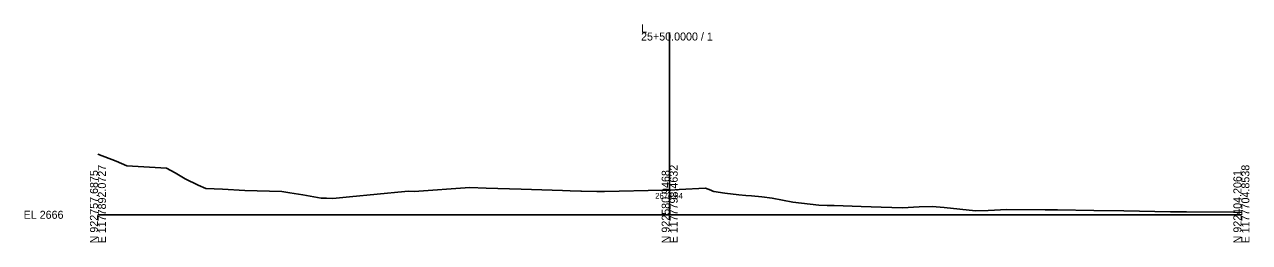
# Model space of a CAD drawing. Extents: x -26 to 1403, y -10 to 9563.
# Drawn here: x 974.3 to 1402.8, y 5490.3 to 5566.5 of the extents above; entities that cross this region are included whole.
import ezdxf

# ---------------------------------------------------------------- set-up
doc = ezdxf.new("R2010")
doc.units = 0
for name, color, linetype in [('Exist Cross Section Cell', 7, 'Continuous'), ('Exist XS Center Line Elevation Label', 7, 'Continuous'), ('Exist XS Ground Line', 7, 'Continuous')]:
    doc.layers.add(name, color=color, linetype=linetype)

msp = doc.modelspace()

# ---------------------------------------------------------------- linework, layer by layer
at = {"layer": 'Exist Cross Section Cell'}
for p, q in [((1200, 5500), (1200, 5563.74)), ((1000, 5500), (1200, 5500)), ((1200, 5500), (1400, 5500))]:
    msp.add_line(p, q, dxfattribs=at)
at = {"layer": 'Exist XS Ground Line'}
for p, q in [((1000, 5521.25), (1006.37, 5518.69)), ((1006.37, 5518.69), (1010.09, 5517.08)), ((1010.09, 5517.08), (1021.98, 5516.42)), ((1021.98, 5516.42), (1023.97, 5516.32)), ((1023.97, 5516.32), (1026.99, 5514.61)), ((1026.99, 5514.61), (1030.47, 5512.6)), ((1030.47, 5512.6), (1035.04, 5510.33)), ((1035.04, 5510.33), (1037.71, 5509.21)), ((1037.71, 5509.21), (1043.54, 5508.94)), ((1043.54, 5508.94), (1051.42, 5508.54)), ((1051.42, 5508.54), (1064.36, 5508.19)), ((1064.36, 5508.19), (1067.11, 5507.71)), ((1067.11, 5507.71), (1071.65, 5506.94)), ((1071.65, 5506.94), (1075.51, 5506.24)), ((1088, 5506.26), (1107.38, 5508.12)), ((1107.38, 5508.12), (1108.68, 5508.3)), ((1108.68, 5508.3), (1110.66, 5508.19)), ((1110.66, 5508.19), (1130.05, 5509.51)), ((1130.05, 5509.51), (1135.76, 5509.35)), ((1135.76, 5509.35), (1148.06, 5508.91)), ((1148.06, 5508.91), (1162.56, 5508.5)), ((1162.56, 5508.5), (1165.22, 5508.4)), ((1165.22, 5508.4), (1168.88, 5508.3)), ((1168.88, 5508.3), (1169.19, 5508.3)), ((1169.19, 5508.3), (1174.53, 5508.15)), ((1174.53, 5508.15), (1174.96, 5508.14)), ((1174.96, 5508.14), (1176.79, 5508.11)), ((1176.79, 5508.11), (1177.26, 5508.1)), ((1177.26, 5508.1), (1197.62, 5508.59)), ((1197.62, 5508.59), (1198.72, 5508.6)), ((1198.72, 5508.6), (1199.33, 5508.62)), ((1199.33, 5508.62), (1200, 5508.64)), ((1200, 5508.64), (1200.4, 5508.65)), ((1200.4, 5508.65), (1203.36, 5508.82)), ((1203.36, 5508.82), (1212.5, 5509.35)), ((1212.5, 5509.35), (1214.42, 5508.55)), ((1214.42, 5508.55), (1215.09, 5508.27)), ((1215.09, 5508.27), (1215.44, 5508.19)), ((1215.44, 5508.19), (1219.25, 5507.5)), ((1219.25, 5507.5), (1224.22, 5506.98)), ((1224.22, 5506.98), (1226.61, 5506.72)), ((1226.61, 5506.72), (1228.57, 5506.58)), ((1075.51, 5506.24), (1078.11, 5505.84)), ((1078.11, 5505.84), (1080.01, 5505.76)), ((1080.01, 5505.76), (1082.18, 5505.69)), ((1082.18, 5505.69), (1088, 5506.26)), ((1228.57, 5506.58), (1232.26, 5506.23)), ((1232.26, 5506.23), (1235.87, 5505.84)), ((1235.87, 5505.84), (1243.09, 5504.39)), ((1243.09, 5504.39), (1252.23, 5503.36)), ((1252.23, 5503.36), (1255.07, 5503.25)), ((1255.07, 5503.25), (1257.56, 5503.22)), ((1257.56, 5503.22), (1266.99, 5502.92)), ((1266.99, 5502.92), (1273.96, 5502.66)), ((1273.96, 5502.66), (1281.47, 5502.45)), ((1281.47, 5502.45), (1287.25, 5502.74)), ((1287.25, 5502.74), (1291.78, 5502.89)), ((1291.78, 5502.89), (1296.04, 5502.52)), ((1296.04, 5502.52), (1306.95, 5501.34)), ((1306.95, 5501.34), (1311.41, 5501.51)), ((1311.41, 5501.51), (1317.92, 5501.84)), ((1317.92, 5501.84), (1331.34, 5501.78)), ((1331.34, 5501.78), (1335.7, 5501.76)), ((1335.7, 5501.76), (1348.42, 5501.52)), ((1348.42, 5501.52), (1358.89, 5501.33)), ((1358.89, 5501.33), (1375.18, 5501.08)), ((1375.18, 5501.08), (1380.84, 5501.03)), ((1380.84, 5501.03), (1397.28, 5500.87)), ((1397.28, 5500.87), (1400, 5500.83))]:
    msp.add_line(p, q, dxfattribs=at)

# ---------------------------------------------------------------- texts
at = {"layer": 'Exist Cross Section Cell'}
for s, p in [('25+50.0000 / 1', (1190, 5560.94)), ('L', (1190, 5563.74)), ('EL 2666', (974, 5498.6))]:
    msp.add_text(s, height=2.8, dxfattribs=at).set_placement(p)
for s, p in [('N 922757.6875', (1000, 5490)), ('E 1177892.0727', (1002.8, 5490)), ('N 922580.9468', (1200, 5490)), ('E 1177798.4632', (1202.8, 5490)), ('N 922404.2061', (1400, 5490)), ('E 1177704.8538', (1402.8, 5490))]:
    msp.add_text(s, height=2.8, rotation=90, dxfattribs=at).set_placement(p)
at = {"layer": 'Exist XS Center Line Elevation Label'}
msp.add_text('2674.64', height=2, dxfattribs=at).set_placement((1194.93, 5505.64))

doc.saveas('drawing.dxf')
